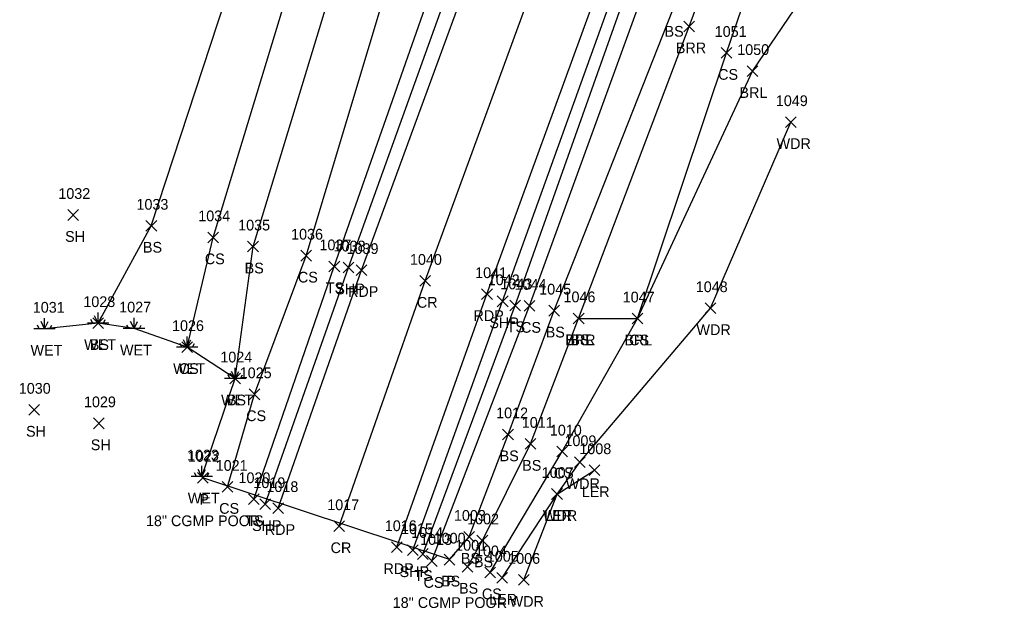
# Model space of a CAD drawing. Extents: x 1554917 to 1555870, y 813367 to 816333.
# Drawn here: x 1554917.3 to 1555102.6, y 813366.9 to 813476.5 of the extents above; entities that cross this region are included whole.
import ezdxf

# ---------------------------------------------------------------- set-up
doc = ezdxf.new("R2010")
doc.units = 0
for name, color, linetype in [('D_A', 7, 'Continuous'), ('D_C', 7, 'Continuous'), ('D_I', 7, 'Continuous'), ('D_TIC', 7, 'Continuous'), ('DCP', 7, 'Continuous'), ('L_A', 7, 'Continuous'), ('L_I', 7, 'Continuous'), ('L_TIC', 7, 'Continuous'), ('LABL', 7, 'Continuous'), ('LARO', 7, 'Continuous'), ('LAWA', 7, 'Continuous'), ('LELB', 7, 'Continuous'), ('LWET', 7, 'Continuous'), ('P_A', 7, 'Continuous'), ('P_I', 7, 'Continuous'), ('P_TIC', 7, 'Continuous'), ('PET', 7, 'Continuous'), ('PRC', 7, 'Continuous'), ('PSP', 7, 'Continuous')]:
    doc.layers.add(name, color=color, linetype=linetype)

msp = doc.modelspace()

# ---------------------------------------------------------------- linework, layer by layer
at = {"layer": 'D_TIC'}
for points in [[(1554950.34, 813390.2), (1554952.34, 813392.2)], [(1554952.34, 813390.2), (1554950.34, 813392.2)], [(1554996.34, 813374.96), (1554998.34, 813376.96)], [(1554998.34, 813374.96), (1554996.34, 813376.96)]]:
    msp.add_lwpolyline(points, dxfattribs=at)
at = {"layer": 'DCP'}
msp.add_lwpolyline([(1554997.34, 813375.96), (1554951.34, 813391.2)], dxfattribs=at)
at = {"layer": 'L_TIC'}
for points in [[(1555041.06, 813474.32), (1555043.06, 813476.32)], [(1555043.06, 813474.32), (1555041.06, 813476.32)], [(1555048, 813469.38), (1555050, 813471.38)], [(1555050, 813469.38), (1555048, 813471.38)], [(1555052.86, 813466), (1555054.86, 813468)], [(1555054.86, 813466), (1555052.86, 813468)], [(1555059.98, 813456.48), (1555061.98, 813458.48)], [(1555061.98, 813456.48), (1555059.98, 813458.48)], [(1554926.19, 813439.18), (1554928.19, 813441.18)], [(1554928.19, 813439.18), (1554926.19, 813441.18)], [(1554940.76, 813437.17), (1554942.76, 813439.17)], [(1554942.76, 813437.17), (1554940.76, 813439.17)], [(1554952.29, 813435.01), (1554954.29, 813437.01)], [(1554954.29, 813435.01), (1554952.29, 813437.01)], [(1554959.72, 813433.3), (1554961.72, 813435.3)], [(1554961.72, 813433.3), (1554959.72, 813435.3)], [(1554969.65, 813431.6), (1554971.65, 813433.6)], [(1554971.65, 813431.6), (1554969.65, 813433.6)], [(1554974.88, 813429.61), (1554976.88, 813431.61)], [(1554976.88, 813429.61), (1554974.88, 813431.61)], [(1555008.62, 813422.34), (1555010.62, 813424.34)], [(1555010.62, 813422.34), (1555008.62, 813424.34)], [(1555011.26, 813422.24), (1555013.26, 813424.24)], [(1555013.26, 813422.24), (1555011.26, 813424.24)], [(1555015.85, 813421.36), (1555017.85, 813423.36)], [(1555017.85, 813421.36), (1555015.85, 813423.36)], [(1555045.04, 813421.81), (1555047.04, 813423.81)], [(1555047.04, 813421.81), (1555045.04, 813423.81)], [(1554930.85, 813419.03), (1554932.85, 813421.03)], [(1554932.85, 813419.03), (1554930.85, 813421.03)], [(1555020.43, 813419.92), (1555022.43, 813421.92)], [(1555022.43, 813419.92), (1555020.43, 813421.92)], [(1555020.43, 813419.92), (1555022.43, 813421.92)], [(1555022.43, 813419.92), (1555020.43, 813421.92)], [(1555020.43, 813419.92), (1555022.43, 813421.92)], [(1555022.43, 813419.92), (1555020.43, 813421.92)], [(1555031.42, 813419.89), (1555033.42, 813421.89)], [(1555033.42, 813419.89), (1555031.42, 813421.89)], [(1555031.42, 813419.89), (1555033.42, 813421.89)], [(1555033.42, 813419.89), (1555031.42, 813421.89)], [(1554947.44, 813414.56), (1554949.44, 813416.56)], [(1554949.44, 813414.56), (1554947.44, 813416.56)], [(1554956.39, 813408.71), (1554958.39, 813410.71)], [(1554958.39, 813408.71), (1554956.39, 813410.71)], [(1554960.01, 813405.77), (1554962.01, 813407.77)], [(1554962.01, 813405.77), (1554960.01, 813407.77)], [(1554918.91, 813402.88), (1554920.91, 813404.88)], [(1554920.91, 813402.88), (1554918.91, 813404.88)], [(1554930.98, 813400.36), (1554932.98, 813402.36)], [(1554932.98, 813400.36), (1554930.98, 813402.36)], [(1555007.26, 813398.3), (1555009.26, 813400.3)], [(1555009.26, 813398.3), (1555007.26, 813400.3)], [(1555011.46, 813396.53), (1555013.46, 813398.53)], [(1555013.46, 813396.53), (1555011.46, 813398.53)], [(1555017.35, 813395.09), (1555019.35, 813397.09)], [(1555019.35, 813395.09), (1555017.35, 813397.09)], [(1555020.64, 813393.11), (1555022.64, 813395.11)], [(1555022.64, 813393.11), (1555020.64, 813395.11)], [(1555023.41, 813391.62), (1555025.41, 813393.62)], [(1555025.41, 813391.62), (1555023.41, 813393.62)], [(1554954.97, 813388.51), (1554956.97, 813390.51)], [(1554956.97, 813388.51), (1554954.97, 813390.51)], [(1554959.86, 813386.22), (1554961.86, 813388.22)], [(1554961.86, 813386.22), (1554959.86, 813388.22)], [(1555016.4, 813387.19), (1555018.4, 813389.19)], [(1555018.4, 813387.19), (1555016.4, 813389.19)], [(1555016.4, 813387.19), (1555018.4, 813389.19)], [(1555018.4, 813387.19), (1555016.4, 813389.19)], [(1555000.03, 813379.2), (1555002.03, 813381.2)], [(1555002.03, 813379.2), (1555000.03, 813381.2)], [(1555002.48, 813378.54), (1555004.48, 813380.54)], [(1555004.48, 813378.54), (1555002.48, 813380.54)], [(1554991.4, 813376.01), (1554993.4, 813378.01)], [(1554993.4, 813376.01), (1554991.4, 813378.01)], [(1554993.08, 813374.71), (1554995.08, 813376.71)], [(1554995.08, 813374.71), (1554993.08, 813376.71)], [(1554996.34, 813374.96), (1554998.34, 813376.96)], [(1554998.34, 813374.96), (1554996.34, 813376.96)], [(1554999.69, 813373.63), (1555001.69, 813375.63)], [(1555001.69, 813373.63), (1554999.69, 813375.63)], [(1555003.95, 813372.58), (1555005.95, 813374.58)], [(1555005.95, 813372.58), (1555003.95, 813374.58)], [(1555006.16, 813371.58), (1555008.16, 813373.58)], [(1555008.16, 813371.58), (1555006.16, 813373.58)], [(1555010.21, 813371.18), (1555012.21, 813373.18)], [(1555012.21, 813371.18), (1555010.21, 813373.18)]]:
    msp.add_lwpolyline(points, dxfattribs=at)
at = {"layer": 'LABL'}
for points in [[(1555021.43, 813420.92), (1555042.06, 813475.32), (1555060.32, 813524.58), (1555067.05, 813522.89), (1555076.12, 813521.23), (1555083.3, 813530.48), (1555085.29, 813534.37), (1555089.23, 813546.42), (1555105.94, 813553.01)], [(1555021.43, 813420.92), (1555032.42, 813420.89), (1555053.86, 813467), (1555085.28, 813513.33), (1555106.23, 813529.94), (1555105.94, 813553.01)]]:
    msp.add_lwpolyline(points, dxfattribs=at)
at = {"layer": 'LARO'}
msp.add_lwpolyline([(1555007.16, 813372.58), (1555017.4, 813388.19), (1555024.41, 813392.62)], dxfattribs=at)
at = {"layer": 'LAWA'}
msp.add_lwpolyline([(1555011.21, 813372.18), (1555017.4, 813388.19), (1555021.64, 813394.11), (1555046.04, 813422.81), (1555060.98, 813457.48)], dxfattribs=at)
at = {"layer": 'LELB'}
for points in [[(1554960.86, 813387.22), (1554975.88, 813430.61), (1554997.67, 813492.71), (1555013.89, 813538.05), (1555028.68, 813579.18), (1555048.82, 813626.54), (1555068.18, 813674.18), (1555096.05, 813749.22), (1555111.01, 813785.1), (1555115.51, 813798.83), (1555119.3, 813812.87), (1555134.87, 813853.17), (1555141.95, 813870.8), (1555155.34, 813907.69), (1555153.32, 813917.67), (1555161.57, 813925.65), (1555168.92, 813938.89)], [(1554992.4, 813377.01), (1555009.62, 813423.34), (1555030.72, 813482.86), (1555047.7, 813528.1), (1555056, 813550.42), (1555062.05, 813566.99), (1555080.33, 813615.57), (1555099.41, 813662.25), (1555114.13, 813700.62), (1555127, 813733.84), (1555152.94, 813799.24), (1555168.16, 813840.25), (1555187.47, 813890.8), (1555199.5, 813919.6)], [(1554997.34, 813375.96), (1555001.03, 813380.2), (1555008.26, 813399.3), (1555016.85, 813422.36), (1555039.01, 813478.41), (1555055.21, 813525.71), (1555062.73, 813548.53), (1555066.84, 813564.4), (1555085.89, 813613.91), (1555101.8, 813661.36), (1555117.2, 813700.9), (1555129.69, 813732.82), (1555155.55, 813797.61), (1555171.4, 813838.65), (1555190.74, 813889.78), (1555201.42, 813914.42), (1555204.39, 813917.83), (1555206.44, 813916.94)], [(1554994.08, 813375.71), (1555012.26, 813423.24), (1555033.65, 813482.08), (1555051.39, 813527.17), (1555057.7, 813549.3), (1555064.2, 813565.75), (1555082.14, 813616.42), (1555099.41, 813662.25)], [(1554955.97, 813389.51), (1554961.01, 813406.77), (1554970.65, 813432.6), (1554989.8, 813496.28), (1555007.9, 813540.38), (1555025.82, 813579.85), (1555048.82, 813626.54)], [(1554957.39, 813409.71), (1554960.72, 813434.3), (1554980.97, 813500.69), (1554989.73, 813523.17), (1554992.08, 813531.74), (1554995.75, 813541.57), (1554998.43, 813550.46), (1555012.26, 813566.6), (1555019.54, 813585.69), (1555024.77, 813597.99)], [(1555004.95, 813373.58), (1555018.35, 813396.09), (1555032.42, 813420.89), (1555049, 813470.38), (1555067.05, 813522.89), (1555075.09, 813530.31)], [(1554931.85, 813420.03), (1554941.76, 813438.17), (1554963.88, 813505.56), (1554971.88, 813527.44)], [(1554948.44, 813415.56), (1554953.29, 813436.01), (1554973.77, 813503.42), (1554980.83, 813522.35)], [(1555000.69, 813374.63), (1555003.48, 813379.54), (1555012.46, 813397.53), (1555021.43, 813420.92)]]:
    msp.add_lwpolyline(points, dxfattribs=at)
at = {"layer": 'LWET'}
for p, q in [((1554921.86, 813418.98), (1554921.86, 813420.98)), ((1554931.85, 813420.03), (1554931.18, 813421.37)), ((1554931.85, 813420.03), (1554931.85, 813422.03)), ((1554931.85, 813420.03), (1554932.51, 813421.37)), ((1554938.54, 813419.02), (1554938.54, 813421.02)), ((1554920.86, 813418.98), (1554920.53, 813419.65)), ((1554921.86, 813418.98), (1554921.19, 813420.31)), ((1554921.86, 813418.98), (1554922.53, 813420.31)), ((1554922.86, 813418.98), (1554923.19, 813419.65)), ((1554933.85, 813420.03), (1554929.85, 813420.03)), ((1554930.85, 813420.03), (1554930.51, 813420.7)), ((1554932.85, 813420.03), (1554933.18, 813420.7)), ((1554937.54, 813419.02), (1554937.21, 813419.68)), ((1554938.54, 813419.02), (1554937.88, 813420.35)), ((1554938.54, 813419.02), (1554939.21, 813420.35)), ((1554939.54, 813419.02), (1554939.88, 813419.68)), ((1554923.86, 813418.98), (1554919.86, 813418.98)), ((1554940.54, 813419.02), (1554936.54, 813419.02)), ((1554948.44, 813415.56), (1554948.44, 813417.56)), ((1554950.44, 813415.56), (1554946.44, 813415.56)), ((1554947.44, 813415.56), (1554947.11, 813416.22)), ((1554948.44, 813415.56), (1554947.78, 813416.89)), ((1554948.44, 813415.56), (1554949.11, 813416.89)), ((1554949.44, 813415.56), (1554949.78, 813416.22)), ((1554957.39, 813409.71), (1554957.39, 813411.71)), ((1554956.39, 813409.71), (1554956.06, 813410.38)), ((1554957.39, 813409.71), (1554956.73, 813411.05)), ((1554957.39, 813409.71), (1554958.06, 813411.05)), ((1554958.39, 813409.71), (1554958.73, 813410.38)), ((1554959.39, 813409.71), (1554955.39, 813409.71)), ((1554951.17, 813391.44), (1554951.17, 813393.44)), ((1554953.17, 813391.44), (1554949.17, 813391.44)), ((1554950.17, 813391.44), (1554949.84, 813392.11)), ((1554951.17, 813391.44), (1554950.5, 813392.77)), ((1554951.17, 813391.44), (1554951.84, 813392.77)), ((1554952.17, 813391.44), (1554952.5, 813392.11))]:
    msp.add_line(p, q, dxfattribs=at)
msp.add_lwpolyline([(1554951.17, 813391.44), (1554957.39, 813409.71), (1554948.44, 813415.56), (1554938.54, 813419.02), (1554931.85, 813420.03), (1554921.86, 813418.98)], dxfattribs=at)
at = {"layer": 'P_TIC'}
for points in [[(1554977.53, 813429.4), (1554979.53, 813431.4)], [(1554979.53, 813429.4), (1554977.53, 813431.4)], [(1554979.95, 813428.92), (1554981.95, 813430.92)], [(1554981.95, 813428.92), (1554979.95, 813430.92)], [(1554991.84, 813426.9), (1554993.84, 813428.9)], [(1554993.84, 813426.9), (1554991.84, 813428.9)], [(1555003.34, 813424.43), (1555005.34, 813426.43)], [(1555005.34, 813424.43), (1555003.34, 813426.43)], [(1555006.26, 813423.1), (1555008.26, 813425.1)], [(1555008.26, 813423.1), (1555006.26, 813425.1)], [(1554962, 813385.3), (1554964, 813387.3)], [(1554964, 813385.3), (1554962, 813387.3)], [(1554964.43, 813384.56), (1554966.43, 813386.56)], [(1554966.43, 813384.56), (1554964.43, 813386.56)], [(1554975.76, 813381.18), (1554977.76, 813383.18)], [(1554977.76, 813381.18), (1554975.76, 813383.18)], [(1554986.55, 813377.28), (1554988.55, 813379.28)], [(1554988.55, 813377.28), (1554986.55, 813379.28)], [(1554989.52, 813376.71), (1554991.52, 813378.71)], [(1554991.52, 813376.71), (1554989.52, 813378.71)]]:
    msp.add_lwpolyline(points, dxfattribs=at)
at = {"layer": 'PET'}
for points in [[(1554965.43, 813385.56), (1554980.95, 813429.92), (1555003.19, 813490.59), (1555019.55, 813535.73), (1555035.2, 813576.47), (1555053.52, 813624.76), (1555072.33, 813672.52), (1555101.11, 813747.71), (1555125.53, 813809.89), (1555141.72, 813851.12), (1555161.36, 813900.53), (1555183.5, 813956.99)], [(1554987.55, 813378.28), (1555004.34, 813425.43), (1555025.15, 813482.53), (1555042.33, 813529.78), (1555057.09, 813568.35), (1555075.57, 813617.35), (1555093.79, 813663.7), (1555108.49, 813702.81), (1555121.71, 813736.27), (1555147.41, 813801.52), (1555163.02, 813841.94), (1555182.57, 813892.25), (1555203.7, 813945.01)]]:
    msp.add_lwpolyline(points, dxfattribs=at)
at = {"layer": 'PRC'}
msp.add_lwpolyline([(1554976.76, 813382.18), (1554992.84, 813427.9), (1555014.07, 813486.01), (1555030.62, 813532.31), (1555046.37, 813573.08), (1555064.69, 813621.19), (1555082.41, 813667.53), (1555112.1, 813744.1), (1555110.69, 813739.79), (1555136.16, 813805.74), (1555152.52, 813846.93), (1555172.03, 813896.18), (1555193.96, 813951.2), (1555206.37, 813983.4), (1555218.13, 814013.22), (1555228.65, 814039.26), (1555237.93, 814064.31), (1555252.22, 814099.76), (1555265.8, 814135.89), (1555275.26, 814160.09), (1555297.17, 814214.77), (1555313.83, 814257.94), (1555329.72, 814298.26), (1555342.03, 814329.92)], dxfattribs=at)
at = {"layer": 'PSP'}
for points in [[(1554990.52, 813377.71), (1555007.26, 813424.1), (1555027.97, 813481.79), (1555045.41, 813528.93), (1555059.94, 813567), (1555096.82, 813663.08), (1555111.75, 813701.59), (1555124.82, 813734.75), (1555150.26, 813800.36), (1555166.19, 813840.91), (1555185.69, 813891.41), (1555197.67, 813922.42), (1555211.91, 813956.86)], [(1554963, 813386.3), (1554978.53, 813430.4), (1555000.44, 813491.39), (1555017.18, 813537.03), (1555032.55, 813577.93), (1555050.86, 813625.69), (1555069.49, 813673.81), (1555098.21, 813748.28), (1555122.69, 813810.6), (1555138.9, 813851.92), (1555160.79, 813906.47), (1555173.05, 813937.33)]]:
    msp.add_lwpolyline(points, dxfattribs=at)

# ---------------------------------------------------------------- texts
at = {"layer": 'D_A'}
for p in [(1554950.71, 813386.2), (1554996.72, 813370.96)]:
    msp.add_text('P', height=2, dxfattribs=at).set_placement(p)
at = {"layer": 'D_C'}
for p in [(1554940.76, 813382.2), (1554986.77, 813366.96)]:
    msp.add_text('18" CGMP POOR', height=2, dxfattribs=at).set_placement(p)
at = {"layer": 'D_I'}
for s, p in [('1022', (1554948.57, 813394.2)), ('1000', (1554994.4, 813378.96))]:
    msp.add_text(s, height=2, dxfattribs=at).set_placement(p)
at = {"layer": 'L_A'}
for s, p in [('BS', (1555037.45, 813473.41)), ('BRR', (1555039.55, 813470.32)), ('CS', (1555047.44, 813465.38)), ('BRL', (1555051.41, 813462)), ('WDR', (1555058.34, 813452.48)), ('SH', (1554925.68, 813435.18)), ('BS', (1554940.2, 813433.17)), ('CS', (1554951.73, 813431.01)), ('BS', (1554959.16, 813429.3)), ('CS', (1554969.09, 813427.6)), ('TS', (1554974.29, 813425.61)), ('TS', (1555008.02, 813418.34)), ('CS', (1555010.7, 813418.24)), ('BS', (1555015.29, 813417.36)), ('WDR', (1555043.4, 813417.81)), ('BRR', (1555018.92, 813415.92)), ('BRL', (1555018.98, 813415.92)), ('BS', (1555019.88, 813415.92)), ('BRL', (1555029.96, 813415.89)), ('CS', (1555030.86, 813415.89)), ('WET', (1554919.24, 813413.98)), ('WET', (1554929.23, 813415.03)), ('BS', (1554930.29, 813415.03)), ('WET', (1554935.92, 813414.02)), ('WET', (1554945.82, 813410.56)), ('CS', (1554946.88, 813410.56)), ('WET', (1554954.77, 813404.71)), ('BS', (1554955.84, 813404.71)), ('CS', (1554959.45, 813401.77)), ('SH', (1554918.4, 813398.88)), ('SH', (1554930.47, 813396.36)), ('BS', (1555006.7, 813394.3)), ('BS', (1555010.9, 813392.53)), ('CS', (1555016.79, 813391.09)), ('WDR', (1555019.01, 813389.11)), ('LER', (1555022, 813387.62)), ('WET', (1554948.55, 813386.44)), ('CS', (1554954.41, 813384.51)), ('TS', (1554959.27, 813382.22)), ('WDR', (1555014.77, 813383.19)), ('LER', (1555014.99, 813383.19)), ('BS', (1554999.47, 813375.2)), ('BS', (1555001.92, 813374.54)), ('TS', (1554990.81, 813372.01)), ('CS', (1554992.52, 813370.71)), ('BS', (1554995.78, 813370.96)), ('BS', (1554999.13, 813369.63)), ('CS', (1555003.39, 813368.58)), ('LER', (1555004.74, 813367.58)), ('WDR', (1555008.57, 813367.18))]:
    msp.add_text(s, height=2, dxfattribs=at).set_placement(p)
at = {"layer": 'L_I'}
for s, p in [('1051', (1555046.8, 813473.38)), ('1050', (1555051, 813470)), ('1049', (1555058.2, 813460.48)), ('1032', (1554924.42, 813443.18)), ('1033', (1554938.99, 813441.17)), ('1034', (1554950.51, 813439.01)), ('1035', (1554957.95, 813437.3)), ('1036', (1554967.82, 813435.6)), ('1037', (1554973.11, 813433.61)), ('1043', (1555006.84, 813426.34)), ('1044', (1555009.49, 813426.24)), ('1045', (1555014.08, 813425.36)), ('1048', (1555043.27, 813425.81)), ('1028', (1554929.08, 813423.03)), ('1028', (1554929.08, 813423.03)), ('1046', (1555018.61, 813423.92)), ('1046', (1555018.61, 813423.92)), ('1046', (1555018.61, 813423.92)), ('1047', (1555029.65, 813423.89)), ('1047', (1555029.65, 813423.89)), ('1031', (1554919.66, 813421.98)), ('1027', (1554935.77, 813422.02)), ('1026', (1554945.62, 813418.56)), ('1026', (1554945.62, 813418.56)), ('1024', (1554954.62, 813412.71)), ('1024', (1554954.62, 813412.71)), ('1025', (1554958.24, 813409.77)), ('1030', (1554917.05, 813406.88)), ('1029', (1554929.2, 813404.36)), ('1012', (1555006.05, 813402.3)), ('1011', (1555010.83, 813400.53)), ('1010', (1555016.06, 813399.09)), ('1009', (1555018.79, 813397.11)), ('1008', (1555021.56, 813395.62)), ('1023', (1554948.4, 813394.44)), ('1021', (1554953.76, 813392.51)), ('1007', (1555014.55, 813391.19)), ('1007', (1555014.55, 813391.19)), ('1020', (1554958.01, 813390.22)), ('1003', (1554998.18, 813383.2)), ('1002', (1555000.63, 813382.54)), ('1014', (1554990.2, 813380.01)), ('1013', (1554991.87, 813378.71)), ('1000', (1554994.4, 813378.96)), ('1001', (1554998.41, 813377.63)), ('1004', (1555002.1, 813376.58)), ('1005', (1555004.31, 813375.58)), ('1006', (1555008.3, 813375.18))]:
    msp.add_text(s, height=2, dxfattribs=at).set_placement(p)
at = {"layer": 'P_A'}
for s, p in [('SHP', (1554976.06, 813425.4)), ('RDP', (1554978.43, 813424.92)), ('CR', (1554991.27, 813422.9)), ('RDP', (1555001.83, 813420.43)), ('SHP', (1555004.79, 813419.1)), ('SHP', (1554960.54, 813381.3)), ('RDP', (1554962.92, 813380.56)), ('CR', (1554975.19, 813377.18)), ('RDP', (1554985.04, 813373.28)), ('SHP', (1554988.05, 813372.71))]:
    msp.add_text(s, height=2, dxfattribs=at).set_placement(p)
at = {"layer": 'P_I'}
for s, p in [('1038', (1554975.75, 813433.4)), ('1039', (1554978.17, 813432.92)), ('1040', (1554989.98, 813430.9)), ('1041', (1555002.14, 813428.43)), ('1042', (1555004.49, 813427.1)), ('1019', (1554960.79, 813389.3)), ('1018', (1554963.22, 813388.56)), ('1017', (1554974.56, 813385.18)), ('1016', (1554985.29, 813381.28)), ('1015', (1554988.31, 813380.71))]:
    msp.add_text(s, height=2, dxfattribs=at).set_placement(p)

doc.saveas('drawing.dxf')
